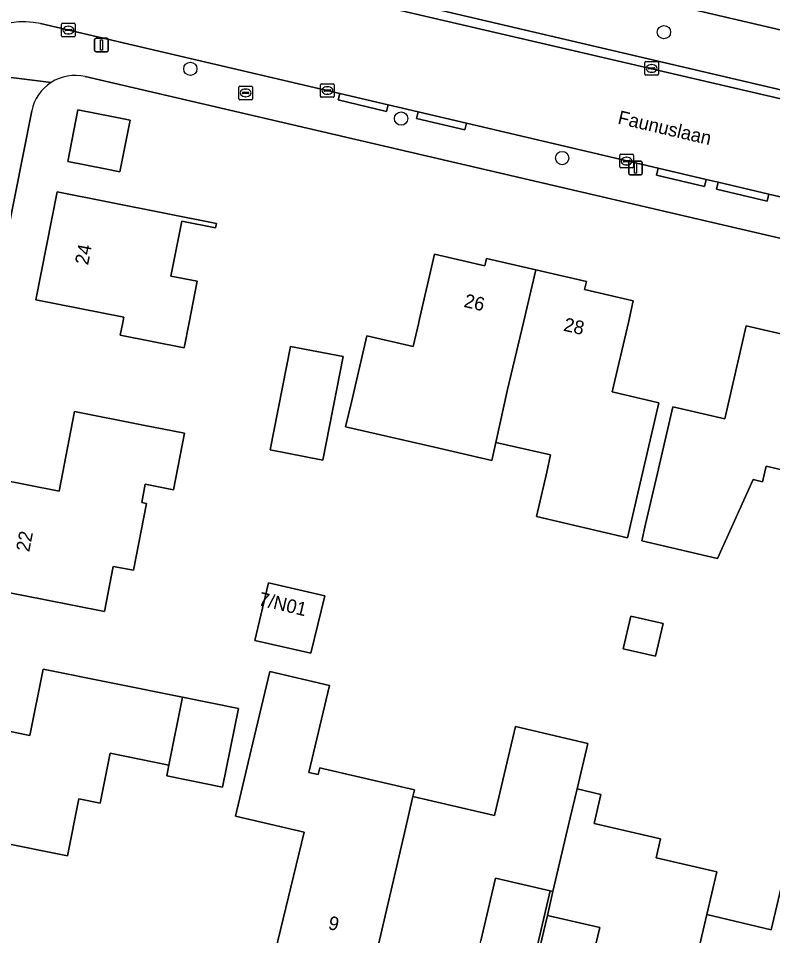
# Model space of a CAD drawing. Extents: x 162184 to 163154, y 385507 to 386516.
# Drawn here: x 162544.8 to 162600.3, y 385954.9 to 386022.3 of the extents above; entities that cross this region are included whole.
import ezdxf

# ---------------------------------------------------------------- set-up
doc = ezdxf.new("R2010")
doc.units = 0
for name, color, linetype in [('IMGEO_Boom', 7, 'Continuous'), ('IMGEO_Brandkraan', 7, 'Continuous'), ('IMGEO_Erf', 7, 'Continuous'), ('IMGEO_Groenvoorziening', 7, 'Continuous'), ('IMGEO_Kolk', 7, 'Continuous'), ('IMGEO_Lichtmast', 7, 'Continuous'), ('IMGEO_Muur', 7, 'Continuous'), ('IMGEO_Openbare_ruimte_label', 7, 'Continuous'), ('IMGEO_Pand', 7, 'Continuous'), ('IMGEO_Pand_nummerreeks', 7, 'Continuous'), ('IMGEO_Rijbaan_lokaal_open', 7, 'Continuous'), ('IMGEO_Voetpad_open', 7, 'Continuous')]:
    doc.layers.add(name, color=color, linetype=linetype)

msp = doc.modelspace()

# ---------------------------------------------------------------- linework, layer by layer
at = {"layer": 'IMGEO_Boom'}
for centre in [(162592.294, 386021.33), (162557.473, 386018.634), (162572.969, 386014.981), (162584.81, 386012.08)]:
    msp.add_circle(centre, 0.489, dxfattribs=at)
at = {"layer": 'IMGEO_Brandkraan'}
for p, q in [((162561.042, 386016.441), (162561.042, 386017.293)), ((162561.117, 386017.367), (162561.969, 386017.367)), ((162562.043, 386017.293), (162562.043, 386016.441)), ((162561.301, 386016.861), (162561.301, 386016.873)), ((162561.739, 386016.824), (162561.341, 386016.824)), ((162561.344, 386016.91), (162561.742, 386016.91)), ((162561.553, 386016.587), (162561.528, 386016.587)), ((162561.53, 386017.147), (162561.555, 386017.147)), ((162561.785, 386016.873), (162561.785, 386016.861)), ((162561.969, 386016.367), (162561.117, 386016.367))]:
    msp.add_line(p, q, dxfattribs=at)
for points in [[(162561.042, 386016.441), (162561.042, 386017.293)], [(162561.117, 386017.367), (162561.969, 386017.367)], [(162562.043, 386017.293), (162562.043, 386016.441)], [(162561.969, 386016.367), (162561.117, 386016.367)]]:
    msp.add_lwpolyline(points, dxfattribs=at)
for centre, radius, start, end in [((162561.119, 386017.291), 0.0765, 91.55205, 178.44795), ((162561.119, 386017.291), 0.0765, 91.55205, 178.44795), ((162561.967, 386017.291), 0.0765, 1.55205, 88.44795), ((162561.967, 386017.291), 0.0765, 1.55205, 88.44795), ((162561.341, 386016.87), 0.0403, 85.87752, 175.75265), ((162561.338, 386016.86), 0.0366, 178.93798, 274.71019), ((162561.742, 386016.867), 0.043, 264.86636, 352.45326), ((162561.746, 386016.872), 0.0386, 1.73085, 96.63898), ((162561.119, 386016.443), 0.0765, 181.55205, 268.44795), ((162561.119, 386016.443), 0.0765, 181.55205, 268.44795), ((162561.967, 386016.443), 0.0765, 271.55205, 358.44795), ((162561.967, 386016.443), 0.0765, 271.55205, 358.44795)]:
    msp.add_arc(centre, radius, start, end, dxfattribs=at)
for centre, major_axis, ratio, start_param, end_param in [((162561.529, 386016.867), (-0.387, 0.002), 0.722429, 4.712389, 7.853982), ((162561.554, 386016.867), (-0.39, 0.002), 0.717154, 1.570796, 4.712389)]:
    msp.add_ellipse(centre, major_axis=major_axis, ratio=ratio, start_param=start_param, end_param=end_param, dxfattribs=at)
at = {"layer": 'IMGEO_Erf'}
for points in [[(162783.536, 385963.718), (162627.446, 386000), (162549.733, 386018.064)], [(162545.809, 386015.54), (162542.711, 386000), (162538.512, 385978.937), (162537.876, 385976.531), (162533.9, 385956.179)], [(162603.474, 385988.583), (162599.811, 385989.429), (162599.547, 385988.285), (162598.842, 385988.448), (162596.229, 385982.642), (162590.657, 385983.929), (162590.945, 385985.177), (162591.811, 385988.927), (162592.936, 385993.798), (162596.769, 385992.913), (162598.347, 385999.747), (162605.66, 385998.057)], [(162563.699, 385953.729), (162565.847, 385962.515), (162560.798, 385963.711), (162561.951, 385968.577), (162563.317, 385974.342), (162567.712, 385973.314), (162566.183, 385966.923), (162566.86, 385966.765), (162566.989, 385967.264), (162567.295, 385967.193), (162573.954, 385965.635), (162573.84, 385965.147), (162579.841, 385963.743), (162581.374, 385970.295), (162586.688, 385969.052), (162585.903, 385965.704), (162587.658, 385965.293), (162587.159, 385963.167), (162592.048, 385962.024), (162591.725, 385960.641), (162596.173, 385959.601), (162595.438, 385956.466), (162600.184, 385955.356), (162601.103, 385959.288)], [(162582.844, 385953.587), (162583.923, 385958.204), (162579.901, 385959.144), (162578.821, 385954.527)], [(162586.895, 385952.64), (162587.567, 385955.514), (162583.726, 385956.412), (162583.054, 385953.538)]]:
    msp.add_lwpolyline(points, dxfattribs=at)
for points in [[(162552.286, 386011.069), (162551.204, 386011.282), (162548.459, 386011.824), (162549.21, 386015.63), (162551.955, 386015.089), (162553.037, 386014.875)], [(162557.007, 385998.129), (162552.317, 385999.055), (162552.503, 386000), (162552.577, 386000.374), (162546.111, 386001.65), (162547.677, 386009.585), (162559.388, 386007.274), (162559.325, 386006.954), (162556.837, 386007.445), (162556.038, 386003.398), (162557.971, 386003.017), (162557.376, 386000)], [(162588.493, 385994.887), (162591.916, 385994.097), (162590.791, 385989.226), (162590.38, 385987.448), (162589.622, 385984.168), (162582.912, 385985.718), (162583.67, 385988.998), (162583.959, 385990.251), (162579.937, 385991.181), (162579.628, 385989.846), (162575.751, 385990.741), (162575.427, 385990.816), (162568.892, 385992.325), (162569.312, 385994.144), (162570.437, 385999.015), (162573.861, 385998.224), (162574.272, 386000), (162574.303, 386000.136), (162575.428, 386005.007), (162579.121, 386004.154), (162579.245, 386004.69), (162582.878, 386003.851), (162586.595, 386002.992), (162586.461, 386002.413), (162590.04, 386001.587), (162589.674, 386000)], [(162567.218, 385989.864), (162563.339, 385990.623), (162564.83, 385998.238), (162568.708, 385997.479)], [(162551.161, 385978.757), (162546.701, 385979.63), (162541.794, 385980.59), (162543.336, 385988.464), (162547.823, 385987.585), (162548.968, 385993.436), (162553.875, 385992.475), (162557.039, 385991.856), (162556.225, 385987.697), (162554.163, 385988.101), (162553.901, 385986.765), (162554.261, 385986.694), (162553.298, 385981.775), (162551.809, 385982.066)], [(162566.339, 385975.672), (162562.21, 385976.627), (162563.208, 385980.85), (162567.368, 385979.887)], [(162591.676, 385975.46), (162589.296, 385976.009), (162589.851, 385978.409), (162592.23, 385977.86)], [(162550.855, 385964.67), (162549.284, 385964.986), (162548.44, 385960.786), (162538.168, 385962.851), (162539.773, 385970.831), (162545.684, 385969.643), (162546.66, 385974.496), (162556.896, 385972.438), (162561.004, 385971.612), (162559.845, 385965.846), (162555.736, 385966.672), (162555.895, 385967.46), (162551.59, 385968.326)]]:
    msp.add_lwpolyline(points, close=True, dxfattribs=at)
for centre, radius, start, end in [((162548.991, 386014.907), 3.243, 76.77532, 122.76644), ((162548.994, 386014.902), 3.249, 122.77162, 168.6818)]:
    msp.add_arc(centre, radius, start, end, dxfattribs=at)
at = {"layer": 'IMGEO_Groenvoorziening'}
msp.add_lwpolyline([(162548.585, 386029.344), (162622.672, 386012.006), (162623.654, 386016.193), (162549.407, 386033.521), (162549.261, 386033.559), (162549.112, 386033.584), (162548.962, 386033.596), (162548.811, 386033.594), (162548.661, 386033.579), (162548.513, 386033.55), (162548.368, 386033.508), (162548.227, 386033.454), (162548.092, 386033.387), (162547.963, 386033.308), (162547.842, 386033.218), (162547.73, 386033.118), (162547.638, 386033.021)], dxfattribs=at)
at = {"layer": 'IMGEO_Kolk'}
for p, q in [((162548.086, 386021.985), (162548.938, 386021.985)), ((162548.011, 386021.059), (162548.011, 386021.911)), ((162548.27, 386021.479), (162548.27, 386021.491)), ((162548.708, 386021.442), (162548.31, 386021.442)), ((162548.313, 386021.528), (162548.711, 386021.528)), ((162548.499, 386021.765), (162548.524, 386021.765)), ((162548.754, 386021.491), (162548.754, 386021.479)), ((162549.012, 386021.911), (162549.012, 386021.059)), ((162548.938, 386020.985), (162548.086, 386020.985)), ((162548.522, 386021.205), (162548.497, 386021.205)), ((162590.887, 386018.242), (162590.887, 386019.094)), ((162590.962, 386019.168), (162591.814, 386019.168)), ((162591.146, 386018.662), (162591.146, 386018.674)), ((162591.584, 386018.625), (162591.186, 386018.625)), ((162591.189, 386018.711), (162591.587, 386018.711)), ((162591.375, 386018.948), (162591.4, 386018.948)), ((162591.63, 386018.674), (162591.63, 386018.662)), ((162591.888, 386019.094), (162591.888, 386018.242)), ((162591.814, 386018.168), (162590.962, 386018.168)), ((162591.398, 386018.388), (162591.373, 386018.388)), ((162567.051, 386016.617), (162567.051, 386017.469)), ((162567.126, 386017.543), (162567.978, 386017.543)), ((162567.539, 386017.323), (162567.564, 386017.323)), ((162568.052, 386017.469), (162568.052, 386016.617)), ((162567.978, 386016.543), (162567.126, 386016.543)), ((162567.31, 386017.037), (162567.31, 386017.049)), ((162567.748, 386017), (162567.35, 386017)), ((162567.353, 386017.086), (162567.751, 386017.086)), ((162567.562, 386016.763), (162567.537, 386016.763)), ((162567.794, 386017.049), (162567.794, 386017.037)), ((162589.043, 386011.426), (162589.043, 386012.278)), ((162589.118, 386012.352), (162589.97, 386012.352)), ((162589.302, 386011.846), (162589.302, 386011.858)), ((162589.74, 386011.809), (162589.342, 386011.809)), ((162589.345, 386011.895), (162589.743, 386011.895)), ((162589.531, 386012.132), (162589.556, 386012.132)), ((162589.786, 386011.858), (162589.786, 386011.846)), ((162590.044, 386012.278), (162590.044, 386011.426)), ((162589.97, 386011.352), (162589.118, 386011.352)), ((162589.554, 386011.572), (162589.529, 386011.572))]:
    msp.add_line(p, q, dxfattribs=at)
for points in [[(162548.086, 386021.985), (162548.938, 386021.985)], [(162548.011, 386021.059), (162548.011, 386021.911)], [(162549.012, 386021.911), (162549.012, 386021.059)], [(162548.938, 386020.985), (162548.086, 386020.985)], [(162590.887, 386018.242), (162590.887, 386019.094)], [(162590.962, 386019.168), (162591.814, 386019.168)], [(162591.888, 386019.094), (162591.888, 386018.242)], [(162591.814, 386018.168), (162590.962, 386018.168)], [(162567.051, 386016.617), (162567.051, 386017.469)], [(162567.126, 386017.543), (162567.978, 386017.543)], [(162568.052, 386017.469), (162568.052, 386016.617)], [(162567.978, 386016.543), (162567.126, 386016.543)], [(162589.043, 386011.426), (162589.043, 386012.278)], [(162589.118, 386012.352), (162589.97, 386012.352)], [(162590.044, 386012.278), (162590.044, 386011.426)], [(162589.97, 386011.352), (162589.118, 386011.352)]]:
    msp.add_lwpolyline(points, dxfattribs=at)
for centre, radius, start, end in [((162548.088, 386021.909), 0.0765, 91.55205, 178.44795), ((162548.088, 386021.909), 0.0765, 91.55205, 178.44795), ((162548.936, 386021.909), 0.0765, 1.55205, 88.44795), ((162548.936, 386021.909), 0.0765, 1.55205, 88.44795), ((162548.31, 386021.488), 0.0403, 85.87752, 175.75265), ((162548.307, 386021.478), 0.0366, 178.93798, 274.71019), ((162548.711, 386021.485), 0.043, 264.86636, 352.45326), ((162548.715, 386021.49), 0.0386, 1.73085, 96.63898), ((162548.088, 386021.061), 0.0765, 181.55205, 268.44795), ((162548.088, 386021.061), 0.0765, 181.55205, 268.44795), ((162548.936, 386021.061), 0.0765, 271.55205, 358.44795), ((162548.936, 386021.061), 0.0765, 271.55205, 358.44795), ((162590.964, 386019.092), 0.0765, 91.55205, 178.44795), ((162590.964, 386019.092), 0.0765, 91.55205, 178.44795), ((162591.186, 386018.671), 0.0403, 85.87752, 175.75265), ((162591.183, 386018.661), 0.0366, 178.93798, 274.71019), ((162591.587, 386018.668), 0.043, 264.86636, 352.45326), ((162591.591, 386018.673), 0.0386, 1.73085, 96.63898), ((162591.812, 386019.092), 0.0765, 1.55205, 88.44795), ((162591.812, 386019.092), 0.0765, 1.55205, 88.44795), ((162590.964, 386018.244), 0.0765, 181.55205, 268.44795), ((162590.964, 386018.244), 0.0765, 181.55205, 268.44795), ((162591.812, 386018.244), 0.0765, 271.55205, 358.44795), ((162591.812, 386018.244), 0.0765, 271.55205, 358.44795), ((162567.128, 386017.467), 0.0765, 91.55205, 178.44795), ((162567.128, 386017.467), 0.0765, 91.55205, 178.44795), ((162567.976, 386017.467), 0.0765, 1.55205, 88.44795), ((162567.976, 386017.467), 0.0765, 1.55205, 88.44795), ((162567.128, 386016.619), 0.0765, 181.55205, 268.44795), ((162567.128, 386016.619), 0.0765, 181.55205, 268.44795), ((162567.35, 386017.046), 0.0403, 85.87752, 175.75265), ((162567.347, 386017.036), 0.0366, 178.93798, 274.71019), ((162567.751, 386017.043), 0.043, 264.86636, 352.45326), ((162567.755, 386017.048), 0.0386, 1.73085, 96.63898), ((162567.976, 386016.619), 0.0765, 271.55205, 358.44795), ((162567.976, 386016.619), 0.0765, 271.55205, 358.44795), ((162589.12, 386012.276), 0.0765, 91.55205, 178.44795), ((162589.12, 386012.276), 0.0765, 91.55205, 178.44795), ((162589.342, 386011.855), 0.0403, 85.87752, 175.75265), ((162589.339, 386011.845), 0.0366, 178.93798, 274.71019), ((162589.743, 386011.852), 0.043, 264.86636, 352.45326), ((162589.747, 386011.857), 0.0386, 1.73085, 96.63898), ((162589.968, 386012.276), 0.0765, 1.55205, 88.44795), ((162589.968, 386012.276), 0.0765, 1.55205, 88.44795), ((162589.12, 386011.428), 0.0765, 181.55205, 268.44795), ((162589.12, 386011.428), 0.0765, 181.55205, 268.44795), ((162589.968, 386011.428), 0.0765, 271.55205, 358.44795), ((162589.968, 386011.428), 0.0765, 271.55205, 358.44795)]:
    msp.add_arc(centre, radius, start, end, dxfattribs=at)
for centre, major_axis, ratio, start_param, end_param in [((162548.498, 386021.485), (-0.387, 0.002), 0.722429, 4.712389, 7.853982), ((162548.523, 386021.485), (-0.39, 0.002), 0.717154, 1.570796, 4.712389), ((162591.374, 386018.668), (-0.387, 0.002), 0.722429, 4.712389, 7.853982), ((162591.399, 386018.668), (-0.39, 0.002), 0.717154, 1.570796, 4.712389), ((162567.538, 386017.043), (-0.387, 0.002), 0.722429, 4.712389, 7.853982), ((162567.563, 386017.043), (-0.39, 0.002), 0.717154, 1.570796, 4.712389), ((162589.53, 386011.852), (-0.387, 0.002), 0.722429, 4.712389, 7.853982), ((162589.555, 386011.852), (-0.39, 0.002), 0.717154, 1.570796, 4.712389)]:
    msp.add_ellipse(centre, major_axis=major_axis, ratio=ratio, start_param=start_param, end_param=end_param, dxfattribs=at)
at = {"layer": 'IMGEO_Lichtmast'}
for p, q in [((162550.439, 386019.989), (162550.439, 386020.789)), ((162550.439, 386020.789), (162550.439, 386019.989)), ((162550.539, 386020.889), (162551.329, 386020.889)), ((162551.329, 386020.889), (162550.539, 386020.889)), ((162551.429, 386020.789), (162551.429, 386019.989)), ((162551.429, 386019.989), (162551.429, 386020.789)), ((162551.329, 386019.889), (162550.539, 386019.889)), ((162550.539, 386019.889), (162551.329, 386019.889)), ((162589.806, 386011.84), (162590.596, 386011.84)), ((162590.596, 386011.84), (162589.806, 386011.84)), ((162589.706, 386010.94), (162589.706, 386011.74)), ((162589.706, 386011.74), (162589.706, 386010.94)), ((162590.696, 386011.74), (162590.696, 386010.94)), ((162590.696, 386010.94), (162590.696, 386011.74)), ((162590.596, 386010.84), (162589.806, 386010.84)), ((162589.806, 386010.84), (162590.596, 386010.84))]:
    msp.add_line(p, q, dxfattribs=at)
for points in [[(162550.859, 386020.764), (162551.009, 386020.764), (162551.009, 386020.014), (162550.859, 386020.014), (162550.859, 386020.764)], [(162590.126, 386011.715), (162590.276, 386011.715), (162590.276, 386010.965), (162590.126, 386010.965), (162590.126, 386011.715)]]:
    msp.add_lwpolyline(points, dxfattribs=at)
for centre, start, end in [((162550.539, 386020.789), 90, 180), ((162550.539, 386020.789), 90, 180), ((162551.329, 386020.789), 0, 90), ((162551.329, 386020.789), 360, 90), ((162550.539, 386019.989), 180, 270), ((162550.539, 386019.989), 180, 270), ((162551.329, 386019.989), 270, 0), ((162551.329, 386019.989), 270, 0), ((162589.806, 386011.74), 90, 180), ((162589.806, 386011.74), 90, 180), ((162590.596, 386011.74), 0, 90), ((162590.596, 386011.74), 360, 90), ((162589.806, 386010.94), 180, 270), ((162589.806, 386010.94), 180, 270), ((162590.596, 386010.94), 270, 0), ((162590.596, 386010.94), 270, 0)]:
    msp.add_arc(centre, 0.1, start, end, dxfattribs=at)
at = {"layer": 'IMGEO_Muur'}
msp.add_lwpolyline([(162584.134, 385958.155), (162583.923, 385958.204), (162582.844, 385953.587), (162583.054, 385953.538), (162583.726, 385956.412)], close=True, dxfattribs=at)
at = {"layer": 'IMGEO_Pand'}
for points in [[(162553.037, 386014.875), (162551.955, 386015.089), (162549.21, 386015.63), (162548.459, 386011.824), (162551.204, 386011.282), (162552.286, 386011.069)], [(162559.388, 386007.274), (162547.677, 386009.585), (162546.111, 386001.65), (162552.577, 386000.374), (162552.503, 386000), (162552.317, 385999.055), (162557.007, 385998.129), (162557.376, 386000), (162557.971, 386003.017), (162556.038, 386003.398), (162556.837, 386007.445), (162559.325, 386006.954)], [(162581.959, 386000), (162582.878, 386003.851), (162579.245, 386004.69), (162579.121, 386004.154), (162575.428, 386005.007), (162574.303, 386000.136), (162574.272, 386000), (162573.861, 385998.224), (162570.437, 385999.015), (162569.312, 385994.144), (162568.892, 385992.325), (162575.427, 385990.816), (162575.751, 385990.741), (162579.628, 385989.846), (162579.937, 385991.181), (162580.779, 385995.055)], [(162591.916, 385994.097), (162588.493, 385994.887), (162589.674, 386000), (162590.04, 386001.587), (162586.461, 386002.413), (162586.595, 386002.992), (162582.878, 386003.851), (162581.959, 386000), (162580.779, 385995.055), (162579.937, 385991.181), (162583.959, 385990.251), (162583.67, 385988.998), (162582.912, 385985.718), (162589.622, 385984.168), (162590.38, 385987.448), (162590.791, 385989.226)], [(162603.474, 385988.583), (162605.66, 385998.057), (162598.347, 385999.747), (162596.769, 385992.913), (162592.936, 385993.798), (162591.811, 385988.927), (162590.945, 385985.177), (162590.657, 385983.929), (162596.229, 385982.642), (162598.842, 385988.448), (162599.547, 385988.285), (162599.811, 385989.429)], [(162568.708, 385997.479), (162564.83, 385998.238), (162563.339, 385990.623), (162567.218, 385989.864)], [(162554.261, 385986.694), (162553.901, 385986.765), (162554.163, 385988.101), (162556.225, 385987.697), (162557.039, 385991.856), (162553.875, 385992.475), (162548.968, 385993.436), (162547.823, 385987.585), (162543.336, 385988.464), (162541.794, 385980.59), (162546.701, 385979.63), (162551.161, 385978.757), (162551.809, 385982.066), (162553.298, 385981.775)], [(162567.368, 385979.887), (162563.208, 385980.85), (162562.21, 385976.627), (162566.339, 385975.672)], [(162591.676, 385975.46), (162592.23, 385977.86), (162589.851, 385978.409), (162589.296, 385976.009)], [(162549.284, 385964.986), (162550.855, 385964.67), (162551.59, 385968.326), (162555.895, 385967.46), (162556.896, 385972.438), (162546.66, 385974.496), (162545.684, 385969.643), (162539.773, 385970.831), (162538.168, 385962.851), (162548.44, 385960.786)], [(162573.84, 385965.147), (162573.954, 385965.635), (162567.295, 385967.193), (162566.989, 385967.264), (162566.86, 385966.765), (162566.183, 385966.923), (162567.712, 385973.314), (162563.317, 385974.342), (162561.951, 385968.577), (162560.798, 385963.711), (162565.847, 385962.515), (162563.699, 385953.729), (162570.78, 385952.073), (162573.239, 385962.578)], [(162556.896, 385972.438), (162555.895, 385967.46), (162555.736, 385966.672), (162559.845, 385965.846), (162561.004, 385971.612)], [(162585.903, 385965.704), (162586.688, 385969.052), (162581.374, 385970.295), (162579.841, 385963.743), (162573.84, 385965.147), (162573.239, 385962.578), (162570.78, 385952.073), (162577.86, 385950.417), (162578.821, 385954.527), (162579.901, 385959.144), (162583.923, 385958.204), (162584.134, 385958.155), (162585.405, 385963.577)], [(162595.438, 385956.466), (162596.173, 385959.601), (162591.725, 385960.641), (162592.048, 385962.024), (162587.159, 385963.167), (162587.658, 385965.293), (162585.903, 385965.704), (162585.405, 385963.577), (162584.134, 385958.155), (162583.726, 385956.412), (162587.567, 385955.514), (162586.895, 385952.64), (162585.83, 385948.086), (162586.206, 385947.998), (162586.311, 385948.444), (162588.221, 385947.998), (162588.151, 385947.699), (162589.877, 385947.295), (162589.953, 385947.62), (162592.828, 385946.948), (162592.726, 385946.509), (162593.085, 385946.425)], [(162603.492, 385954.743), (162603.602, 385955.211), (162604.377, 385958.522), (162601.103, 385959.288), (162600.184, 385955.356), (162595.438, 385956.466), (162593.085, 385946.425), (162593.443, 385946.341), (162593.546, 385946.783), (162599.947, 385945.286), (162599.846, 385944.851), (162600.203, 385944.768), (162601.447, 385950.085), (162602.353, 385949.874)]]:
    msp.add_lwpolyline(points, close=True, dxfattribs=at)
at = {"layer": 'IMGEO_Rijbaan_lokaal_open'}
msp.add_lwpolyline([(162546.46, 386021.965), (162568.455, 386016.817), (162572.017, 386015.983), (162574.218, 386015.468), (162577.774, 386014.633), (162591.86, 386011.338), (162595.4, 386010.51), (162596.269, 386010.307), (162600.013, 386009.431), (162615.081, 386005.903), (162621.185, 386004.474), (162629.259, 386002.584), (162630.86, 386009.478), (162549.167, 386028.469)], dxfattribs=at)
msp.add_arc((162545.211, 386016.017), 6.077, 78.14133, 158.08048, dxfattribs=at)
at = {"layer": 'IMGEO_Voetpad_open'}
for points in [[(162549.407, 386033.521), (162623.654, 386016.193), (162622.672, 386012.006), (162624.3, 386011.641), (162625.242, 386015.858), (162649.077, 386010.279)], [(162615.081, 386005.903), (162600.013, 386009.431), (162599.892, 386008.916), (162596.148, 386009.791), (162596.269, 386010.307), (162595.4, 386010.51), (162595.28, 386009.995), (162591.74, 386010.822), (162591.86, 386011.338), (162577.774, 386014.633), (162577.659, 386014.147), (162574.104, 386014.987), (162574.218, 386015.468), (162572.017, 386015.983), (162571.905, 386015.507), (162568.345, 386016.346), (162568.455, 386016.817), (162546.46, 386021.965)], [(162541.889, 386018.283), (162547.236, 386017.634)], [(162547.236, 386017.634), (162541.889, 386018.283)], [(162549.733, 386018.064), (162627.446, 386000), (162783.536, 385963.718)], [(162542.711, 386000), (162545.809, 386015.54)]]:
    msp.add_lwpolyline(points, dxfattribs=at)
for points in [[(162624.3, 386011.641), (162622.672, 386012.006), (162548.585, 386029.344), (162549.167, 386028.469), (162630.86, 386009.478), (162635.584, 386008.379), (162653.515, 386004.211), (162654.412, 386004.751), (162652.711, 386005.036), (162649.671, 386005.765)], [(162568.455, 386016.817), (162568.345, 386016.346), (162571.905, 386015.507), (162572.017, 386015.983)], [(162577.774, 386014.633), (162574.218, 386015.468), (162574.104, 386014.987), (162577.659, 386014.147)], [(162591.86, 386011.338), (162591.74, 386010.822), (162595.28, 386009.995), (162595.4, 386010.51)], [(162600.013, 386009.431), (162596.269, 386010.307), (162596.148, 386009.791), (162599.892, 386008.916)]]:
    msp.add_lwpolyline(points, close=True, dxfattribs=at)
for centre, radius, start, end in [((162545.211, 386016.017), 6.077, 78.14133, 158.08048), ((162548.991, 386014.907), 3.243, 76.77532, 122.76644), ((162548.994, 386014.902), 3.249, 122.77162, 168.6818)]:
    msp.add_arc(centre, radius, start, end, dxfattribs=at)

# ---------------------------------------------------------------- texts
at = {"layer": 'IMGEO_Openbare_ruimte_label'}
msp.add_text('Faunuslaan', height=1, rotation=346.82507, dxfattribs=at).set_placement((162588.838, 386014.616))
at = {"layer": 'IMGEO_Pand_nummerreeks'}
for s, rotation, p in [('24', 78.83594, (162549.952, 386004.171)), ('26', 346.8277, (162577.529, 386001.146)), ('28', 347.32044, (162584.853, 385999.393)), ('22', 78.91921, (162545.625, 385983.083)), ('7/N01', 346.53885, (162562.42, 385979.222)), ('9', 346.83343, (162567.546, 385955.418))]:
    msp.add_text(s, height=1, rotation=rotation, dxfattribs=at).set_placement(p)

doc.saveas('drawing.dxf')
